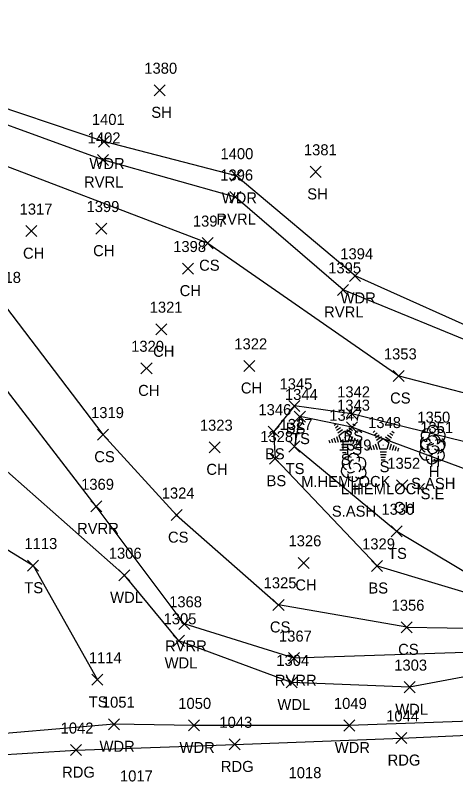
# Model space of a CAD drawing. Extents: x 1621633 to 1624015, y 417863 to 420979.
# Drawn here: x 1622191.2 to 1622271, y 418146.1 to 418283.9 of the extents above; entities that cross this region are included whole.
import ezdxf

# ---------------------------------------------------------------- set-up
doc = ezdxf.new("R2010")
doc.units = 0
for name, color, linetype in [('L_A', 7, 'Continuous'), ('L_C', 7, 'Continuous'), ('L_I', 7, 'Continuous'), ('L_TIC', 7, 'Continuous'), ('LAWA', 7, 'Continuous'), ('LAWE', 7, 'Continuous'), ('LELB', 7, 'Continuous'), ('LTC', 7, 'Continuous'), ('LTD', 7, 'Continuous'), ('P_A', 7, 'Continuous'), ('P_I', 7, 'Continuous'), ('P_TIC', 7, 'Continuous'), ('PEU', 7, 'Continuous')]:
    doc.layers.add(name, color=color, linetype=linetype)

msp = doc.modelspace()

# ---------------------------------------------------------------- linework, layer by layer
at = {"layer": 'L_TIC'}
for points in [[(1622216.36, 418269.26), (1622218.36, 418271.26)], [(1622218.36, 418269.26), (1622216.36, 418271.26)], [(1622206.28, 418259.97), (1622208.28, 418261.97)], [(1622208.28, 418259.97), (1622206.28, 418261.97)], [(1622206.09, 418256.63), (1622208.09, 418258.63)], [(1622208.09, 418256.63), (1622206.09, 418258.63)], [(1622230.24, 418253.76), (1622232.24, 418255.76)], [(1622232.24, 418253.76), (1622230.24, 418255.76)], [(1622244.61, 418254.47), (1622246.61, 418256.47)], [(1622246.61, 418254.47), (1622244.61, 418256.47)], [(1622230.09, 418249.9), (1622232.09, 418251.9)], [(1622232.09, 418249.9), (1622230.09, 418251.9)], [(1622205.82, 418244.18), (1622207.82, 418246.18)], [(1622207.82, 418244.18), (1622205.82, 418246.18)], [(1622193.13, 418243.72), (1622195.13, 418245.72)], [(1622195.13, 418243.72), (1622193.13, 418245.72)], [(1622225.07, 418241.54), (1622227.07, 418243.54)], [(1622227.07, 418241.54), (1622225.07, 418243.54)], [(1622221.5, 418236.93), (1622223.5, 418238.93)], [(1622223.5, 418236.93), (1622221.5, 418238.93)], [(1622251.77, 418235.61), (1622253.77, 418237.61)], [(1622253.77, 418235.61), (1622251.77, 418237.61)], [(1622249.59, 418233.06), (1622251.59, 418235.06)], [(1622251.59, 418233.06), (1622249.59, 418235.06)], [(1622216.69, 418225.93), (1622218.69, 418227.93)], [(1622218.69, 418225.93), (1622216.69, 418227.93)], [(1622232.58, 418219.28), (1622234.58, 418221.28)], [(1622234.58, 418219.28), (1622232.58, 418221.28)], [(1622213.98, 418218.84), (1622215.98, 418220.84)], [(1622215.98, 418218.84), (1622213.98, 418220.84)], [(1622259.66, 418217.46), (1622261.66, 418219.46)], [(1622261.66, 418217.46), (1622259.66, 418219.46)], [(1622240.76, 418212.02), (1622242.76, 418214.02)], [(1622242.76, 418212.02), (1622240.76, 418214.02)], [(1622241.75, 418210.1), (1622243.75, 418212.1)], [(1622243.75, 418210.1), (1622241.75, 418212.1)], [(1622251.2, 418210.57), (1622253.2, 418212.57)], [(1622253.2, 418210.57), (1622251.2, 418212.57)], [(1622251.19, 418208.16), (1622253.19, 418210.16)], [(1622253.19, 418208.16), (1622251.19, 418210.16)], [(1622206.08, 418206.82), (1622208.08, 418208.82)], [(1622208.08, 418206.82), (1622206.08, 418208.82)], [(1622237, 418207.35), (1622239, 418209.35)], [(1622239, 418207.35), (1622237, 418209.35)], [(1622226.33, 418204.53), (1622228.33, 418206.53)], [(1622228.33, 418204.53), (1622226.33, 418206.53)], [(1622240.77, 418204.67), (1622242.77, 418206.67)], [(1622242.77, 418204.67), (1622240.77, 418206.67)], [(1622237.27, 418202.47), (1622239.27, 418204.47)], [(1622239.27, 418202.47), (1622237.27, 418204.47)], [(1622260.29, 418197.62), (1622262.29, 418199.62)], [(1622262.29, 418197.62), (1622260.29, 418199.62)], [(1622204.88, 418193.82), (1622206.88, 418195.82)], [(1622206.88, 418193.82), (1622204.88, 418195.82)], [(1622219.43, 418192.23), (1622221.43, 418194.23)], [(1622221.43, 418192.23), (1622219.43, 418194.23)], [(1622259.31, 418189.29), (1622261.31, 418191.29)], [(1622261.31, 418189.29), (1622259.31, 418191.29)], [(1622242.45, 418183.57), (1622244.45, 418185.57)], [(1622244.45, 418183.57), (1622242.45, 418185.57)], [(1622193.43, 418183.07), (1622195.43, 418185.07)], [(1622195.43, 418183.07), (1622193.43, 418185.07)], [(1622255.73, 418183.01), (1622257.73, 418185.01)], [(1622257.73, 418183.01), (1622255.73, 418185.01)], [(1622209.97, 418181.32), (1622211.97, 418183.32)], [(1622211.97, 418181.32), (1622209.97, 418183.32)], [(1622237.89, 418175.95), (1622239.89, 418177.95)], [(1622239.89, 418175.95), (1622237.89, 418177.95)], [(1622220.82, 418172.51), (1622222.82, 418174.51)], [(1622222.82, 418172.51), (1622220.82, 418174.51)], [(1622261.12, 418171.89), (1622263.12, 418173.89)], [(1622263.12, 418171.89), (1622261.12, 418173.89)], [(1622219.84, 418169.43), (1622221.84, 418171.43)], [(1622221.84, 418169.43), (1622219.84, 418171.43)], [(1622240.72, 418166.29), (1622242.72, 418168.29)], [(1622242.72, 418166.29), (1622240.72, 418168.29)], [(1622205.1, 418162.37), (1622207.1, 418164.37)], [(1622207.1, 418162.37), (1622205.1, 418164.37)], [(1622240.27, 418161.89), (1622242.27, 418163.89)], [(1622242.27, 418161.89), (1622240.27, 418163.89)], [(1622261.62, 418161.03), (1622263.62, 418163.03)], [(1622263.62, 418161.03), (1622261.62, 418163.03)], [(1622208.11, 418154.31), (1622210.11, 418156.31)], [(1622210.11, 418154.31), (1622208.11, 418156.31)], [(1622222.6, 418154.09), (1622224.6, 418156.09)], [(1622224.6, 418154.09), (1622222.6, 418156.09)], [(1622250.71, 418154.08), (1622252.71, 418156.08)], [(1622252.71, 418154.08), (1622250.71, 418156.08)]]:
    msp.add_lwpolyline(points, dxfattribs=at)
at = {"layer": 'LAWA'}
for points in [[(1622334.14, 418235.62), (1622304.57, 418226.13), (1622279.17, 418224.78), (1622252.77, 418236.61), (1622231.24, 418254.76), (1622207.28, 418260.97), (1622182.84, 418269.19), (1622160.31, 418273.27), (1622129.81, 418281.16), (1622108.44, 418283.87), (1622096.55, 418277.43), (1622071.98, 418274.52), (1622045.71, 418270.54), (1622021.3, 418265.82)], [(1622320.21, 418157.08), (1622282.22, 418156.15), (1622251.71, 418155.08), (1622223.6, 418155.09), (1622209.11, 418155.31), (1622180.88, 418152.89), (1622152.12, 418150.87), (1622117.37, 418144.74), (1622094.14, 418141.69), (1622062.96, 418134.28), (1622030.01, 418125.89), (1622002.09, 418113.22), (1622001.94, 418118.19), (1622004.41, 418142.61), (1621992.55, 418166.21), (1621982.92, 418190.96), (1621974.22, 418213.57), (1621987.21, 418225.09), (1622016.71, 418238.58), (1622052.18, 418242.59)], [(1622294.12, 418161.35), (1622295.35, 418165.31), (1622279.05, 418165.1), (1622262.62, 418162.03), (1622241.27, 418162.89), (1622220.84, 418170.43), (1622210.97, 418182.32), (1622187.59, 418203.03), (1622170.53, 418217.1), (1622143.74, 418224.16), (1622117.62, 418234.62), (1622098.7, 418232.3), (1622072.64, 418230.63)]]:
    msp.add_lwpolyline(points, dxfattribs=at)
at = {"layer": 'LAWE'}
for points in [[(1622333.17, 418232.98), (1622304.92, 418224.43), (1622278.58, 418222.6), (1622250.59, 418234.06), (1622231.09, 418250.9), (1622207.09, 418257.63), (1622185.14, 418265.61), (1622157.85, 418271.29), (1622128.42, 418279.11), (1622109.18, 418281.03), (1622103.42, 418276.53), (1622081.07, 418269.59), (1622054.89, 418266.85), (1622024.68, 418262.78), (1621999.35, 418261.34), (1621980.1, 418259.35), (1621959.54, 418247.53), (1621949.11, 418230.91), (1621945.67, 418206.62), (1621950.84, 418182.3), (1621958.69, 418157.04), (1621962.92, 418133.77), (1621970.23, 418110.89)], [(1622323.31, 418180.93), (1622300.82, 418170.32), (1622276.31, 418168.44), (1622241.72, 418167.29), (1622221.82, 418173.51), (1622205.88, 418194.82), (1622185.97, 418220.63), (1622162.23, 418235.42), (1622129.82, 418241.7), (1622106.38, 418246.35), (1622101.43, 418250.25), (1622073.09, 418248.58), (1622043.82, 418244.16), (1622014.93, 418241.31), (1621989.87, 418234.25), (1621972.68, 418220.99), (1621964.49, 418204.33), (1621969.88, 418176.14), (1621978.91, 418154.62), (1621984.37, 418139.62), (1621989.94, 418122.86), (1621991.15, 418115.14)]]:
    msp.add_lwpolyline(points, dxfattribs=at)
at = {"layer": 'LELB'}
for points in [[(1622226.07, 418242.54), (1622182.37, 418259.24)], [(1622119.32, 418258.12), (1622145.14, 418254.74), (1622164.68, 418245.26), (1622188.41, 418232.33), (1622207.08, 418207.82), (1622220.43, 418193.23), (1622238.89, 418176.95)], [(1622226.07, 418242.54), (1622260.66, 418218.46)], [(1622012.96, 418144.68), (1622025.55, 418152.7), (1622030.18, 418148.41), (1622040.54, 418132.85), (1622043.38, 418133.51), (1622037.79, 418144.79), (1622034.62, 418151.12), (1622038.47, 418156.73), (1622040.15, 418173.27), (1622045.7, 418182.18), (1622058.58, 418190.33), (1622063.65, 418207.42), (1622064.55, 418215.49), (1622074.9, 418223.54), (1622095.34, 418218.88), (1622118.02, 418219.75), (1622146.4, 418210.35), (1622169.6, 418199.38), (1622194.43, 418184.07), (1622206.1, 418163.37)], [(1622260.66, 418218.46), (1622281.63, 418213.07), (1622307.86, 418216.47)], [(1622238.27, 418203.47), (1622256.73, 418184.01), (1622278.85, 418177.36), (1622295.37, 418179.62), (1622315.97, 418194.44), (1622314.3, 418205.05), (1622299.28, 418202.1), (1622274.82, 418205.96), (1622252.2, 418211.57), (1622241.76, 418213.02), (1622238, 418208.35)], [(1622241.77, 418205.67), (1622260.31, 418190.29), (1622277.84, 418179.86), (1622294.48, 418182.42), (1622309.03, 418194.87), (1622299.7, 418198.49), (1622274.7, 418200.82), (1622252.19, 418209.16), (1622242.75, 418211.1)], [(1622242.75, 418211.1), (1622241.77, 418205.67)], [(1622238, 418208.35), (1622238.27, 418203.47)], [(1622262.12, 418172.89), (1622238.89, 418176.95)], [(1622262.12, 418172.89), (1622291.36, 418172.44), (1622300.12, 418173.8)]]:
    msp.add_lwpolyline(points, dxfattribs=at)
at = {"layer": 'LTC'}
for p, q in [((1622248.98, 418209.54), (1622249.34, 418209.8)), ((1622249.19, 418209.08), (1622249.72, 418209.46)), ((1622249.4, 418208.61), (1622250.1, 418209.12)), ((1622249.61, 418208.15), (1622250.49, 418208.78)), ((1622251.27, 418208.74), (1622252.08, 418208.15)), ((1622251.64, 418209.09), (1622252.32, 418208.59)), ((1622252.01, 418209.43), (1622252.56, 418209.04)), ((1622252.38, 418209.78), (1622252.8, 418209.48)), ((1622249.38, 418207.47), (1622249.71, 418206.45)), ((1622249.83, 418207.69), (1622250.85, 418208.42)), ((1622249.83, 418207.69), (1622250.22, 418206.5)), ((1622250.85, 418208.42), (1622251.84, 418207.7)), ((1622251.84, 418207.7), (1622251.45, 418206.5)), ((1622252.28, 418207.43), (1622251.94, 418206.39)), ((1622256.01, 418208.22), (1622256.36, 418208.48)), ((1622256.22, 418207.75), (1622256.75, 418208.14)), ((1622256.43, 418207.29), (1622257.13, 418207.8)), ((1622256.64, 418206.82), (1622257.52, 418207.46)), ((1622258.29, 418207.41), (1622259.1, 418206.82)), ((1622258.66, 418207.76), (1622259.34, 418207.27)), ((1622259.04, 418208.11), (1622259.58, 418207.71)), ((1622259.41, 418208.46), (1622259.83, 418208.15)), ((1622248.01, 418206.82), (1622248.17, 418206.35)), ((1622248.47, 418207.04), (1622248.68, 418206.39)), ((1622248.92, 418207.25), (1622249.2, 418206.42)), ((1622251.45, 418206.5), (1622250.22, 418206.5)), ((1622251.41, 418206), (1622250.27, 418206)), ((1622252.73, 418207.18), (1622252.44, 418206.29)), ((1622253.17, 418206.93), (1622252.93, 418206.2)), ((1622253.61, 418206.68), (1622253.43, 418206.1)), ((1622255.95, 418205.93), (1622256.22, 418205.1)), ((1622256.41, 418206.15), (1622256.74, 418205.13)), ((1622256.86, 418206.37), (1622257.87, 418207.1)), ((1622256.86, 418206.37), (1622257.25, 418205.17)), ((1622257.87, 418207.1), (1622258.87, 418206.38)), ((1622258.87, 418206.38), (1622258.48, 418205.17)), ((1622259.31, 418206.1), (1622258.97, 418205.07)), ((1622251.33, 418205.5), (1622250.34, 418205.5)), ((1622251.25, 418205), (1622250.41, 418205)), ((1622255.04, 418205.5), (1622255.19, 418205.03)), ((1622255.5, 418205.71), (1622255.71, 418205.06)), ((1622258.48, 418205.17), (1622257.25, 418205.17)), ((1622258.44, 418204.67), (1622257.3, 418204.67)), ((1622259.75, 418205.85), (1622259.46, 418204.97)), ((1622260.2, 418205.6), (1622259.96, 418204.87)), ((1622260.64, 418205.35), (1622260.45, 418204.78)), ((1622251.16, 418204.5), (1622250.49, 418204.5)), ((1622258.36, 418204.17), (1622257.37, 418204.17)), ((1622258.27, 418203.67), (1622257.44, 418203.67)), ((1622258.19, 418203.17), (1622257.51, 418203.17))]:
    msp.add_line(p, q, dxfattribs=at)
at = {"layer": 'LTD'}
for p, q in [((1622266.82, 418206.99), (1622266.82, 418206.99)), ((1622266.82, 418206.99), (1622266.82, 418206.99)), ((1622266.68, 418205.11), (1622266.68, 418205.11)), ((1622266.68, 418205.11), (1622266.68, 418205.11)), ((1622252.47, 418201.94), (1622252.47, 418201.94)), ((1622252.47, 418201.94), (1622252.47, 418201.94))]:
    msp.add_line(p, q, dxfattribs=at)
for centre in [(1622266.87, 418208.43), (1622266.72, 418206.54), (1622252.52, 418203.37)]:
    msp.add_arc(centre, 1.05, 335.5272, 180.9563, dxfattribs=at)
for centre, major_axis, ratio, start_param, end_param in [((1622266.03, 418207.66), (1.21, -0.51), 0.895232, 1.570796, 4.712389), ((1622267.86, 418207.58), (-1.14, -0.48), 0.949671, 1.570796, 4.712389), ((1622265.74, 418206.29), (0.58, -1.04), 0.959034, 3.141593, 6.283185), ((1622266.61, 418207.45), (-0.208, -0.792), 0.645439, 3.141593, 6.283185), ((1622267.32, 418206.83), (-0.5, 0.667), 0.989748, 3.141593, 6.283185), ((1622265.88, 418205.78), (1.21, -0.51), 0.895232, 1.570796, 4.712389), ((1622266.36, 418206.24), (-0.625, -0.083), 0.423636, 0, 3.141593), ((1622266.47, 418205.57), (-0.208, -0.792), 0.645439, 3.141593, 6.283185), ((1622267.82, 418206.16), (-1.09, 0.79), 0.841452, 1.570796, 4.712389), ((1622267.72, 418205.69), (-1.14, -0.48), 0.949671, 1.570796, 4.712389), ((1622265.59, 418204.4), (0.58, -1.04), 0.959034, 3.141593, 6.283185), ((1622266.82, 418205.49), (0.26, 1.06), 0.942809, 1.570796, 4.712389), ((1622267.18, 418204.94), (-0.5, 0.667), 0.989748, 3.141593, 6.283185), ((1622267.68, 418204.28), (-1.09, 0.79), 0.841452, 1.570796, 4.712389), ((1622251.68, 418202.6), (1.21, -0.51), 0.895232, 1.570796, 4.712389), ((1622252.26, 418202.39), (-0.208, -0.792), 0.645439, 3.141593, 6.283185), ((1622253.51, 418202.52), (-1.14, -0.48), 0.949671, 1.570796, 4.712389), ((1622266.68, 418203.61), (0.26, 1.06), 0.942809, 1.570796, 4.712389), ((1622266.22, 418204.36), (-0.625, -0.083), 0.423636, 0, 3.141593), ((1622251.39, 418201.23), (0.58, -1.04), 0.959034, 3.141593, 6.283185), ((1622252.97, 418201.77), (-0.5, 0.667), 0.989748, 3.141593, 6.283185), ((1622253.47, 418201.1), (-1.09, 0.79), 0.841452, 1.570796, 4.712389), ((1622252.47, 418200.44), (0.26, 1.06), 0.942809, 1.570796, 4.712389), ((1622252.01, 418201.19), (-0.625, -0.083), 0.423636, 0, 3.141593)]:
    msp.add_ellipse(centre, major_axis=major_axis, ratio=ratio, start_param=start_param, end_param=end_param, dxfattribs=at)
at = {"layer": 'P_TIC'}
for points in [[(1622260.16, 418151.81), (1622262.16, 418153.81)], [(1622262.16, 418151.81), (1622260.16, 418153.81)], [(1622229.95, 418150.66), (1622231.95, 418152.66)], [(1622231.95, 418150.66), (1622229.95, 418152.66)], [(1622201.2, 418149.62), (1622203.2, 418151.62)], [(1622203.2, 418149.62), (1622201.2, 418151.62)]]:
    msp.add_lwpolyline(points, dxfattribs=at)
at = {"layer": 'PEU'}
msp.add_lwpolyline([(1622170.97, 418148.68), (1622202.2, 418150.62), (1622230.95, 418151.66), (1622261.16, 418152.81), (1622291.64, 418154.17), (1622319.92, 418154.72)], dxfattribs=at)

# ---------------------------------------------------------------- texts
at = {"layer": 'L_A'}
for s, p in [('SH', (1622215.85, 418265.26)), ('WDR', (1622204.64, 418255.97)), ('RVRL', (1622203.66, 418252.63)), ('WDR', (1622228.6, 418249.76)), ('SH', (1622244.1, 418250.47)), ('RVRL', (1622227.65, 418245.9)), ('CH', (1622192.61, 418239.72)), ('CH', (1622205.31, 418240.18)), ('CS', (1622224.51, 418237.54)), ('CH', (1622220.99, 418232.93)), ('WDR', (1622250.13, 418231.61)), ('RVRL', (1622247.15, 418229.06)), ('CH', (1622216.17, 418221.93)), ('CH', (1622232.07, 418215.28)), ('CH', (1622213.47, 418214.84)), ('CS', (1622259.1, 418213.46)), ('BS', (1622240.21, 418208.02)), ('TS', (1622241.16, 418206.1)), ('BS', (1622250.65, 418206.57)), ('TS', (1622250.6, 418204.16)), ('CS', (1622205.52, 418202.82)), ('BS', (1622236.44, 418203.35)), ('S', (1622250.17, 418202.33)), ('H', (1622266.26, 418201.99)), ('CH', (1622225.82, 418200.53)), ('TS', (1622240.18, 418200.67)), ('S', (1622257.2, 418201.01)), ('H', (1622266.11, 418200.11)), ('BS', (1622236.72, 418198.47)), ('H', (1622251.9, 418196.94)), ('CH', (1622259.78, 418193.62)), ('RVRR', (1622202.4, 418189.82)), ('CS', (1622218.87, 418188.23)), ('TS', (1622258.72, 418185.29)), ('CH', (1622241.94, 418179.57)), ('TS', (1622192.84, 418179.07)), ('BS', (1622255.17, 418179.01)), ('WDL', (1622208.39, 418177.32)), ('CS', (1622237.33, 418171.95)), ('RVRR', (1622218.33, 418168.51)), ('CS', (1622260.56, 418167.89)), ('WDL', (1622218.26, 418165.43)), ('RVRR', (1622238.23, 418162.29)), ('TS', (1622204.51, 418158.37)), ('WDL', (1622238.69, 418157.89)), ('WDL', (1622260.04, 418157.03)), ('WDR', (1622206.47, 418150.31)), ('WDR', (1622220.96, 418150.09)), ('WDR', (1622249.07, 418150.08))]:
    msp.add_text(s, height=2, dxfattribs=at).set_placement(p)
at = {"layer": 'L_C'}
for s, p in [('M.HEMLOCK', (1622242.98, 418198.33)), ('L.HEMLOCK', (1622250.18, 418197.01)), ('S.ASH', (1622262.9, 418197.99)), ('S.E', (1622264.63, 418196.11)), ('S.ASH', (1622248.55, 418192.94))]:
    msp.add_text(s, height=2, dxfattribs=at).set_placement(p)
at = {"layer": 'L_I'}
for s, p in [('1380', (1622214.58, 418273.26)), ('1401', (1622205.08, 418263.97)), ('1402', (1622204.32, 418260.63)), ('1400', (1622228.38, 418257.76)), ('1381', (1622243.49, 418258.47)), ('1396', (1622228.34, 418253.9)), ('1399', (1622204.12, 418248.18)), ('1317', (1622192, 418247.72)), ('1397', (1622223.38, 418245.54)), ('1398', (1622219.81, 418240.93)), ('1394', (1622250.08, 418239.61)), ('1395', (1622247.89, 418237.06)), ('1318', (1622186.29, 418235.33)), ('1321', (1622215.56, 418229.93)), ('1322', (1622230.89, 418223.28)), ('1320', (1622212.2, 418222.84)), ('1353', (1622257.97, 418221.46)), ('1345', (1622239.07, 418216.02)), ('1344', (1622240.06, 418214.1)), ('1342', (1622249.51, 418214.57)), ('1343', (1622249.5, 418212.16)), ('1319', (1622204.94, 418210.82)), ('1346', (1622235.25, 418211.35)), ('1347', (1622248.09, 418210.33)), ('1350', (1622264.04, 418209.99)), ('1323', (1622224.64, 418208.53)), ('1327', (1622239.08, 418208.67)), ('1348', (1622255.12, 418209.01)), ('1351', (1622264.55, 418208.11)), ('1328', (1622235.58, 418206.47)), ('1349', (1622249.77, 418204.94)), ('1352', (1622258.6, 418201.62)), ('1369', (1622203.14, 418197.82)), ('1324', (1622217.74, 418196.23)), ('1330', (1622257.53, 418193.29)), ('1326', (1622240.7, 418187.57)), ('1113', (1622192.87, 418187.07)), ('1329', (1622254.03, 418187.01)), ('1306', (1622208.15, 418185.32)), ('1325', (1622236.2, 418179.95)), ('1368', (1622219.08, 418176.51)), ('1356', (1622259.37, 418175.89)), ('1305', (1622218.07, 418173.43)), ('1367', (1622238.98, 418170.29)), ('1114', (1622204.54, 418166.37)), ('1304', (1622238.5, 418165.89)), ('1303', (1622259.85, 418165.03)), ('1051', (1622206.9, 418158.31)), ('1050', (1622220.74, 418158.09)), ('1049', (1622248.93, 418158.08))]:
    msp.add_text(s, height=2, dxfattribs=at).set_placement(p)
at = {"layer": 'LTC'}
for p in [(1622250.73, 418207.44), (1622257.76, 418206.11)]:
    msp.add_text('.', height=1.04, rotation=270, dxfattribs=at).set_placement(p)
at = {"layer": 'P_A'}
for p in [(1622258.65, 418147.81), (1622228.44, 418146.66), (1622199.69, 418145.62)]:
    msp.add_text('RDG', height=2, dxfattribs=at).set_placement(p)
at = {"layer": 'P_I'}
for s, p in [('1044', (1622258.39, 418155.81)), ('1043', (1622228.18, 418154.66)), ('1042', (1622199.43, 418153.62)), ('1017', (1622210.18, 418144.94)), ('1018', (1622240.71, 418145.53))]:
    msp.add_text(s, height=2, dxfattribs=at).set_placement(p)

doc.saveas('drawing.dxf')
